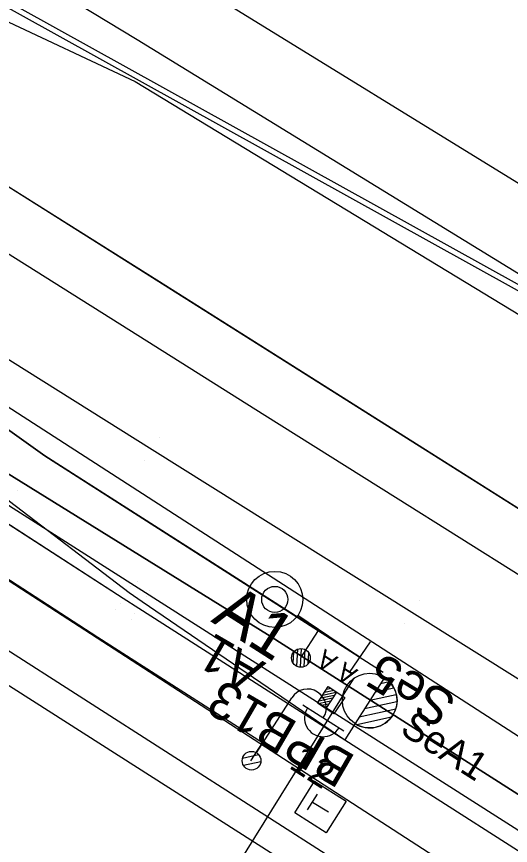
# Model space of a CAD drawing. Extents: x -621145 to -620023, y -1122866 to -1121971.
# Drawn here: x -620754.88 to -620728.46, y -1122419.37 to -1122375.04 of the extents above; entities that cross this region are included whole.
import ezdxf

# ---------------------------------------------------------------- set-up
doc = ezdxf.new("R2010")
doc.units = 0
for name, color, linetype in [('060601_EOV', 7, 'Continuous'), ('060604_ROZVODY_SEE', 7, 'Continuous'), ('CETIN', 7, 'Continuous'), ('Level 10', 7, 'Continuous'), ('PS 06-14-01_trasa_sdělovací_nové', 7, 'Continuous'), ('SEE', 7, 'Continuous'), ('SSZT', 7, 'Continuous'), ('SSZT-DK', 7, 'Continuous'), ('UZEMNĚNÍ', 7, 'Continuous'), ('Vrstva 1', 7, 'Continuous'), ('Vrstva 2', 7, 'Continuous'), ('Vrstva 25', 7, 'Continuous'), ('Vrstva 3', 7, 'Continuous'), ('Vrstva 53', 7, 'Continuous'), ('Vrstva 55', 7, 'Continuous'), ('Vrstva 56', 7, 'Continuous'), ('Vrstva 6', 7, 'Continuous'), ('Vrstva 62', 7, 'Continuous'), ('ČD-T', 7, 'Continuous')]:
    doc.layers.add(name, color=color, linetype=linetype)

# ---------------------------------------------------------------- blocks, each defined once
blk = doc.blocks.new('C535')
at = {"layer": 'Level 10'}
for p, q in [((-0.05, 0.05), (0.05, 0.05)), ((0, 0.05), (0, -0.05))]:
    blk.add_line(p, q, dxfattribs=at)
blk.add_lwpolyline([(-0.1, 0.1), (0.1, 0.1), (0.1, -0.1), (-0.1, -0.1), (-0.1, 0.1)], dxfattribs=at)

msp = doc.modelspace()

# ---------------------------------------------------------------- linework, layer by layer
at = {"layer": '060601_EOV'}
msp.add_lwpolyline([(-620538.89, -1122521.208), (-620599.215, -1122483.216), (-620683.524, -1122429.444), (-620756.33, -1122383.523), (-620765.796, -1122398.395), (-620784.65, -1122386.386), (-620822.218, -1122362.419), (-620817.53, -1122355.085), (-620826.407, -1122348.082), (-620839.916, -1122337.943), (-620848.842, -1122331.997), (-620848.834, -1122331.986)], dxfattribs=at)
at = {"layer": '060604_ROZVODY_SEE'}
for points in [[(-620742.353, -1122414.851), (-620741.729, -1122413.876), (-620750.529, -1122408.246), (-620763.558, -1122399.82), (-620784.65, -1122386.386), (-620822.218, -1122362.419), (-620817.53, -1122355.085), (-620826.407, -1122348.082), (-620839.916, -1122337.943), (-620854.567, -1122328.184), (-620868.06, -1122319.694), (-620885.37, -1122308.815), (-620912.868, -1122291.527), (-620913.325, -1122292.255)], [(-620443.525, -1122595.005), (-620456.111, -1122587.123), (-620447.823, -1122572.959), (-620450.948, -1122571.455), (-620470.592, -1122561.479), (-620499.61, -1122545.574), (-620522.038, -1122531.471), (-620538.89, -1122521.208), (-620599.215, -1122483.216), (-620683.524, -1122429.444), (-620756.33, -1122383.523), (-620765.796, -1122398.395)]]:
    msp.add_lwpolyline(points, dxfattribs=at)
at = {"layer": 'CETIN'}
msp.add_lwpolyline([(-620926.411, -1122268.704), (-620748.436, -1122376.269), (-620484.52, -1122538.147)], dxfattribs=at)
at = {"layer": 'PS 06-14-01_trasa_sdělovací_nové'}
msp.add_lwpolyline([(-620538.89, -1122521.208), (-620538.89, -1122521.208), (-620599.215, -1122483.216), (-620683.524, -1122429.444), (-620756.33, -1122383.523), (-620761.979, -1122392.397), (-620753.366, -1122398.538), (-620735.257, -1122410.106), (-620735.257, -1122410.106)], dxfattribs=at)
at = {"layer": 'SEE'}
msp.add_lwpolyline([(-620545.407, -1122539.454), (-620611.375, -1122497.696), (-620665.569, -1122462.755), (-620686.035, -1122449.829), (-620727.537, -1122423.183), (-620794.508, -1122379.862), (-620815.52, -1122356.954), (-620832.168, -1122344.663), (-620847.808, -1122332.592), (-620908.257, -1122294.686)], dxfattribs=at)
at = {"layer": 'SSZT'}
msp.add_lwpolyline([(-620879.238, -1122313.316), (-620842.993, -1122336.61), (-620835.049, -1122343.251), (-620812.66, -1122358.949), (-620764.902, -1122389.752), (-620688.594, -1122438.969), (-620596.981, -1122496.725), (-620576.744, -1122509.484), (-620506.746, -1122556.123), (-620447.293, -1122593.619), (-620363.271, -1122647.563), (-620313.966, -1122679.218), (-620306.51, -1122669.289), (-620273.137, -1122696.274), (-620258.422, -1122709.142), (-620248.072, -1122696.094)], dxfattribs=at)
at = {"layer": 'SSZT-DK'}
msp.add_lwpolyline([(-620927.288, -1122269.995), (-620900.269, -1122286.467), (-620889.147, -1122293.455), (-620783.743, -1122358.818), (-620712.751, -1122398.176), (-620653.117, -1122435.232), (-620617.363, -1122456.738), (-620574.425, -1122482.604)], dxfattribs=at)
at = {"layer": 'UZEMNĚNÍ'}
msp.add_lwpolyline([(-620742.353, -1122414.851), (-620741.729, -1122413.876), (-620750.529, -1122408.246), (-620763.558, -1122399.82), (-620784.65, -1122386.386), (-620822.218, -1122362.419), (-620817.53, -1122355.085), (-620826.407, -1122348.082), (-620838.671, -1122338.878), (-620840.227, -1122340.951)], dxfattribs=at)
at = {"layer": 'Vrstva 1'}
for p in [(-620739.666, -1122409.343), (-620736.513, -1122409.303)]:
    msp.add_line(p, (-620738.733, -1122407.885), dxfattribs=at)
for points in [[(-620851.644, -1122327.076), (-620840.376, -1122334.591), (-620831.192, -1122341.263), (-620824.896, -1122346.12), (-620811.348, -1122356.777), (-620800.849, -1122364.554), (-620800.095, -1122365.072), (-620796.174, -1122367.693), (-620795.017, -1122368.443), (-620786.31, -1122373.928), (-620764.415, -1122387.671), (-620747.632, -1122398.188), (-620733.731, -1122406.893), (-620718.349, -1122416.524), (-620703.006, -1122426.145), (-620686.977, -1122436.203), (-620670.849, -1122446.339), (-620652.243, -1122458.025), (-620632.992, -1122470.125), (-620616.992, -1122480.169), (-620599.707, -1122491.044), (-620582.331, -1122501.971), (-620566.971, -1122511.728)], [(-620851.644, -1122327.076), (-620843.142, -1122332.434), (-620837.627, -1122335.918), (-620832.116, -1122339.39), (-620828.016, -1122341.966), (-620823.788, -1122344.633), (-620816.971, -1122348.943), (-620810.355, -1122353.089), (-620803.86, -1122357.181), (-620803.36, -1122357.495), (-620800.131, -1122359.525), (-620798.65, -1122360.458), (-620794.421, -1122363.123), (-620788.102, -1122367.105), (-620781.123, -1122371.499), (-620774.168, -1122375.876), (-620767.514, -1122380.058), (-620763.223, -1122382.761), (-620756.392, -1122387.049), (-620748.87, -1122391.776), (-620741.59, -1122396.353), (-620734.607, -1122400.749), (-620727.792, -1122405.031)], [(-620811.348, -1122356.777), (-620801.076, -1122364.818), (-620794.028, -1122370.353), (-620788.085, -1122375.002), (-620768.881, -1122390.097), (-620768.433, -1122390.449), (-620761.754, -1122395.699), (-620755.252, -1122400.953), (-620748.862, -1122405.846), (-620748.158, -1122406.325), (-620737.324, -1122413.726), (-620723.134, -1122422.771)], [(-620807.154, -1122369.064), (-620804.382, -1122370.836), (-620783.306, -1122384.278), (-620762.208, -1122397.716), (-620749.177, -1122406.143), (-620748.333, -1122406.684), (-620737.324, -1122413.726)], [(-620781.123, -1122371.499), (-620774.168, -1122375.876), (-620767.514, -1122380.058), (-620763.223, -1122382.761), (-620756.392, -1122387.049), (-620748.87, -1122391.776), (-620741.59, -1122396.353), (-620734.607, -1122400.749), (-620727.792, -1122405.031)], [(-620538.89, -1122521.208), (-620599.215, -1122483.216), (-620683.524, -1122429.444), (-620747.38, -1122389.133), (-620756.33, -1122383.523)], [(-620738.733, -1122407.885), (-620753.366, -1122398.538), (-620761.979, -1122392.397)]]:
    msp.add_lwpolyline(points, dxfattribs=at)
at = {"layer": 'Vrstva 2'}
for p, q in [((-620739.823, -1122407.057), (-620736.513, -1122409.303)), ((-620739.693, -1122409.842), (-620739.639, -1122408.846)), ((-620737.075, -1122410.131), (-620735.952, -1122408.476)), ((-620740.081, -1122409.618), (-620740.049, -1122409.025)), ((-620739.89, -1122409.788), (-620739.84, -1122408.876)), ((-620739.491, -1122409.81), (-620739.441, -1122408.897)), ((-620739.282, -1122409.662), (-620739.25, -1122409.068)), ((-620735.198, -1122410.39), (-620736.771, -1122412.858)), ((-620735.404, -1122410.709), (-620734.938, -1122410.606)), ((-620737.89, -1122411.082), (-620738.403, -1122411.189)), ((-620738.046, -1122410.98), (-620738.301, -1122411.033)), ((-620735.689, -1122411.157), (-620734.698, -1122410.938)), ((-620737.981, -1122411.503), (-620738.708, -1122411.655)), ((-620737.879, -1122411.347), (-620738.606, -1122411.499)), ((-620737.778, -1122411.192), (-620738.505, -1122411.344)), ((-620735.974, -1122411.604), (-620734.564, -1122411.292)), ((-620738.083, -1122411.658), (-620738.723, -1122411.792)), ((-620738.185, -1122411.813), (-620738.568, -1122411.893)), ((-620738.286, -1122411.969), (-620738.412, -1122411.995)), ((-620736.26, -1122412.051), (-620734.526, -1122411.667)), ((-620736.545, -1122412.498), (-620734.594, -1122412.066)), ((-620736.771, -1122412.858), (-620737.324, -1122413.726)), ((-620736.674, -1122412.911), (-620734.82, -1122412.501))]:
    msp.add_line(p, q, dxfattribs=at)
for points in [[(-620761.754, -1122395.699), (-620755.252, -1122400.953), (-620748.862, -1122405.846), (-620748.158, -1122406.325), (-620737.324, -1122413.726)], [(-620762.208, -1122397.716), (-620755.9, -1122401.819), (-620749.177, -1122406.143), (-620748.333, -1122406.684), (-620737.324, -1122413.726)]]:
    msp.add_lwpolyline(points, dxfattribs=at)
for points in [[(-620738.336, -1122412.045), (-620738.775, -1122411.757), (-620738.2, -1122410.879), (-620737.761, -1122411.167)], [(-620738.336, -1122412.045), (-620738.775, -1122411.757), (-620738.2, -1122410.879), (-620737.761, -1122411.167)], [(-620737.897, -1122412.333), (-620738.775, -1122411.757), (-620738.2, -1122410.879), (-620737.322, -1122411.454)]]:
    msp.add_lwpolyline(points, close=True, dxfattribs=at)
for centre, radius in [((-620741.065, -1122406.215), 1.5), ((-620741.065, -1122406.215), 0.7), ((-620739.666, -1122409.343), 0.5), ((-620735.984, -1122411.624), 1.464)]:
    msp.add_circle(centre, radius, dxfattribs=at)
msp.add_arc((-620735.985, -1122411.624), 1.463, 237.5048, 57.4657, dxfattribs=at)
at = {"layer": 'Vrstva 25'}
for p, q in [((-620742.039, -1122414.418), (-620740.153, -1122411.469)), ((-620739.563, -1122411.847), (-620737.373, -1122413.248)), ((-620742.789, -1122414.704), (-620741.93, -1122414.516)), ((-620742.745, -1122415.078), (-620741.81, -1122414.873))]:
    msp.add_line(p, q, dxfattribs=at)
msp.add_circle((-620742.308, -1122414.839), 0.5, dxfattribs=at)
for centre, start, end in [((-620739.31, -1122412.008), 327.3946, 147.3946), ((-620738.474, -1122412.557), 146.6921, 328.0972)]:
    msp.add_arc(centre, 1, start, end, dxfattribs=at)
at = {"layer": 'Vrstva 53'}
for p, q in [((-620741.46, -1122408.09), (-620821.12, -1122358.76)), ((-620768.63, -1122369.09), (-620748.53, -1122378.52)), ((-620748.53, -1122378.52), (-620702.13, -1122406.7)), ((-620679.51, -1122447.56), (-620741.46, -1122408.09))]:
    msp.add_line(p, q, dxfattribs=at)
at = {"layer": 'Vrstva 55'}
for p, q in [((-620866.03, -1122298.98), (-620688.16, -1122408.5)), ((-620821.12, -1122358.76), (-620741.46, -1122408.09)), ((-620684.91, -1122455.63), (-620825.92, -1122365.89)), ((-620645.72, -1122471.03), (-620807.67, -1122367.84)), ((-620768.63, -1122369.09), (-620748.53, -1122378.52)), ((-620748.53, -1122378.52), (-620702.13, -1122406.7)), ((-620741.46, -1122408.09), (-620679.51, -1122447.56))]:
    msp.add_line(p, q, dxfattribs=at)
at = {"layer": 'Vrstva 56'}
msp.add_line((-620810.36, -1122373.73), (-620648.08, -1122477.56), dxfattribs=at)
at = {"layer": 'Vrstva 6'}
for p, q in [((-620736.841, -1122410.421), (-620737.379, -1122411.265)), ((-620737.11, -1122410.843), (-620751.294, -1122433.601))]:
    msp.add_line(p, q, dxfattribs=at)
at = {"layer": 'Vrstva 62'}
for p, q in [((-620747.244, -1122397.576), (-620747.244, -1122397.576)), ((-620748.021, -1122398.8), (-620748.021, -1122398.8)), ((-620754.809, -1122400.37), (-620754.809, -1122400.37)), ((-620748.417, -1122405.264), (-620748.417, -1122405.264)), ((-620748.789, -1122405.538), (-620748.789, -1122405.538)), ((-620747.772, -1122405.758), (-620747.772, -1122405.758)), ((-620747.946, -1122406.078), (-620747.946, -1122406.078)), ((-620749.321, -1122406.446), (-620749.321, -1122406.446)), ((-620733.329, -1122406.279), (-620733.329, -1122406.279)), ((-620749.565, -1122406.748), (-620749.565, -1122406.748)), ((-620748.582, -1122406.948), (-620748.582, -1122406.948)), ((-620748.721, -1122407.29), (-620748.721, -1122407.29)), ((-620734.133, -1122407.506), (-620734.133, -1122407.506)), ((-620736.939, -1122413.117), (-620736.939, -1122413.117)), ((-620737.709, -1122414.336), (-620737.709, -1122414.336))]:
    msp.add_line(p, q, dxfattribs=at)
at = {"layer": 'ČD-T'}
msp.add_lwpolyline([(-620927.12, -1122269.748), (-620900.082, -1122286.233), (-620888.96, -1122293.22), (-620783.556, -1122358.583), (-620712.564, -1122397.941), (-620652.93, -1122434.998), (-620617.176, -1122456.504), (-620574.237, -1122482.37)], dxfattribs=at)

# ---------------------------------------------------------------- block references
at = {"layer": 'PS 06-14-01_trasa_sdělovací_nové', "xscale": 10, "yscale": 10.000000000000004, "rotation": 57.86154890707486}
msp.add_blockref('C535', (-620738.622, -1122417.316), dxfattribs=at)

# ---------------------------------------------------------------- texts
at = {"layer": 'Vrstva 2'}
msp.add_text('A1', height=2.5, rotation=327.4857, dxfattribs=at).set_placement((-620744.527, -1122407.381))
at = {"layer": 'Vrstva 25'}
msp.add_text('12', height=1.5, rotation=327.3946, dxfattribs=at).set_placement((-620740.366, -1122415.196))
at = {"layer": 'Vrstva 3'}
for s, rotation, p in [('A1', 149.8236, (-620741.5, -1122409.63)), ('Se5', 148.8786, (-620731.224, -1122411.469)), ('BPB13', 149.8236, (-620736.662, -1122414.634))]:
    msp.add_text(s, height=2, rotation=rotation, dxfattribs=at).set_placement(p)
at = {"layer": 'Vrstva 6'}
for s, height, rotation, p in [('A A ', 1, 147.4857, (-620736.572, -1122410)), ('SeA1', 1.5, 327.4857, (-620734.433, -1122413.346))]:
    msp.add_text(s, height=height, rotation=rotation, dxfattribs=at).set_placement(p)

doc.saveas('drawing.dxf')
